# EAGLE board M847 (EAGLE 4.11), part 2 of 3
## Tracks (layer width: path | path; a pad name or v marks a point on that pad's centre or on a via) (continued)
C30 (continued)
  Top 0.254: E3.12 247.65,105.41 D354.C 247.01,116.21 245.75,116.21 D360.C 245.11,118.11 246.38,119.38 246.38,131.45 | 246.38,131.45 247.01,131.45 D353.C | 246.38,131.45 245.75,131.45 D359.C 245.11,133.35 246.38,134.62 246.38,146.69 | 246.38,146.69 247.01,146.69 D352.C | 246.38,146.69 245.75,146.69 D358.C 245.11,148.59 246.38,149.86 246.38,161.93 | D349.C 247.01,192.41 245.75,192.41 D355.C 245.11,191.77 246.38,190.5 246.38,177.17 | 246.38,161.93 247.01,161.93 D351.C | 246.38,161.93 245.75,161.93 D357.C 245.11,163.83 246.38,165.1 246.38,177.17 | 246.38,177.17 247.01,177.17 D350.C | 246.38,177.17 245.75,177.17 D356.C
C31
  Top 0.254: E3.10 254,99.06 D366.C 253.37,116.21 252.09,116.21 D372.C 251.46,118.11 252.73,119.38 252.73,131.45 | 252.73,131.45 253.37,131.45 D365.C | 252.73,131.45 252.09,131.45 D371.C 251.46,133.35 252.73,134.62 252.73,146.69 | 252.73,146.69 253.37,146.69 D364.C | 252.73,146.69 252.09,146.69 D370.C 251.46,148.59 252.73,149.86 252.73,161.93 | 252.73,161.93 253.37,161.93 D363.C | 252.73,161.93 252.09,161.93 D369.C 251.46,163.83 252.73,165.1 252.73,177.17 | 252.73,177.17 253.37,177.17 D362.C | 252.73,177.17 252.09,177.17 D368.C 251.46,179.07 250.19,180.34 250.19,190.5 251.46,191.77 D367.C
  Bottom 0.254: D367.C 252.09,192.41 253.37,192.41 D361.C
C32  (via drill 0.61)
  Top 0.254: v257.81,96.52 D384.C 258.44,116.21 259.71,116.21 D378.C 260.35,118.11 259.08,119.38 259.08,131.45 | 259.08,131.45 259.71,131.45 D377.C | 259.08,131.45 258.44,131.45 D383.C 257.81,133.35 259.08,134.62 259.08,146.69 | 259.08,146.69 259.71,146.69 D376.C | 259.08,146.69 258.44,146.69 D382.C 257.81,148.59 259.08,149.86 259.08,161.93 | D373.C 259.71,192.41 258.44,192.41 D379.C 257.81,191.77 259.08,190.5 259.08,177.17 | 259.08,161.93 259.71,161.93 D375.C | 259.08,161.93 258.44,161.93 D381.C 257.81,163.83 259.08,165.1 259.08,177.17 | 259.08,177.17 259.71,177.17 D374.C | 259.08,177.17 258.44,177.17 D380.C
  Bottom 0.254: v257.81,96.52 252.73,91.44 E3.8
CLR_GO\  (via drill 0.61)
  Top 0.254: v186.06,74.93 185.42,75.57 185.42,101.6 184.15,102.87 180.97,102.87 180.97,100.97 E10.4
  Bottom 0.254: v186.06,74.93 163.83,74.93 161.29,77.47 144.78,77.47 143.51,76.2 E18.13
D2\  (via drill 0.61)
  Top 0.254: E18.1 133.35,80.01 133.35,104.14 130.81,106.68 E19.4 | v13.34,107.95 13.34,93.35 E37.10
  Bottom 0.254: v13.34,107.95 14.61,109.22 105.41,109.22 106.05,109.86 | 106.05,109.86 107.95,111.76 E23.1 | 106.05,109.86 107.95,107.95 127,107.95 128.27,106.68 E19.4
D4  (via drill 0.61)
  Top 0.254: 17.14,86.36 17.14,97.16 E37.13 | 17.14,86.36 17.14,70.49 E36.10 | v102.23,99.06 v102.23,87.63 102.23,78.11 E22.2 | 17.14,86.36 25.4,86.36 v25.4,87
  Bottom 0.254: v102.23,99.06 103.5,100.33 146.05,100.33 148.59,97.79 161.29,97.79 163.83,100.33 166.37,100.33 170.18,104.14 E13.13 | v25.4,87 26.04,87.63 v102.23,87.63
DATA00\
  Top 0.254: E7.12 219.07,33.66 219.07,13.97 U$2.AR1
  Bottom 0.254: E4.10 234.95,35.56 233.68,34.29 223.52,34.29 222.25,35.56 E7.12
DATA01\  (via drill 0.61)
  Top 0.254: v223.52,41.91 223.52,40.64 E7.13 | v217.81,34.93 217.81,13.97 U$2.AS1
  Bottom 0.254: v223.52,41.91 233.68,41.91 234.95,43.18 E4.13 | E7.13 v217.81,34.93
DATA02\
  Top 0.254: E7.4 211.46,36.2 211.46,13.97 U$2.AU1
  Bottom 0.254: E7.4 214.63,38.1 215.9,39.37 226.06,39.37 227.33,38.1 E4.4
DATA03\  (via drill 0.61)
  Top 0.254: 210.82,38.1 208.28,35.56 208.28,13.97 U$2.AV1 | E7.3 210.82,38.1 | v210.19,48.26 210.82,47.63 210.82,38.1
  Bottom 0.254: v210.19,48.26 224.79,48.26 227.33,45.72 E4.1
DATA04\
  Top 0.254: E11.4 160.66,36.2 160.66,35.56 E14.10 151.13,31.75 151.13,13.97 U$2.BR1
DATA05\  (via drill 0.61)
  Top 0.254: E14.13 160.66,43.18 160.66,42.55 E11.3 | v145.41,41.91 145.41,14.61 146.05,13.97 U$2.BS1
  Bottom 0.254: v145.41,41.91 152.4,41.91 153.67,43.18 E14.13
DATA06\  (via drill 0.61)
  Top 0.254: v141.6,36.83 141.6,13.97 U$2.BU1
  Bottom 0.254: 144.78,36.83 v141.6,36.83 130.81,36.83 130.18,36.2 116.2,36.2 115.57,35.56 E21.10 | 144.78,36.83 146.05,38.1 E14.4 | 144.78,36.83 167.64,36.83 168.91,35.56 E11.12
DATA07\  (via drill 0.61)
  Top 0.254: v165.74,43.18 165.74,42.55 E11.13 | v137.16,48.9 137.16,13.97 U$2.BV1
  Bottom 0.254: 137.16,46.99 144.78,46.99 146.05,45.72 E14.1 148.59,45.72 149.86,44.45 164.47,44.45 v165.74,43.18 | 137.16,46.99 109.22,46.99 107.95,45.72 E21.1 | v137.16,48.9 137.16,46.99
DATA08\  (via drill 0.61)
  Top 0.254: E32.10 36.83,29.21 40.01,29.21 40.01,31.12 39.37,31.75 36.83,31.75 35.56,33.02 35.56,43.18 E29.1 | v55.88,34.29 59.69,38.1 E26.4 | v17.78,31.75 17.78,13.97 U$2.DR1
  Bottom 0.254: 33.02,34.29 v55.88,34.29 | 33.02,34.29 31.75,35.56 E32.10 | v17.78,31.75 20.32,34.29 33.02,34.29
DATA09\  (via drill 0.61)
  Top 0.254: v33.02,40.64 E32.13 28.57,41.28 28.57,31.12 v24.13,26.67 | v16.51,19.05 16.51,15.88 14.61,13.97 U$2.DS1
  Bottom 0.254: E26.3 52.07,40.64 50.8,39.37 40.64,39.37 39.37,38.1 E29.4 35.56,38.1 v33.02,40.64 | v16.51,19.05 v24.13,26.67
DATA10\  (via drill 0.61)
  Top 0.254: v10.16,33.02 10.16,30.48 8.26,28.58 8.26,13.97 U$2.DU1
  Bottom 0.254: 25.4,36.83 24.13,38.1 E32.4 | 25.4,36.83 43.18,36.83 44.45,35.56 E29.10 53.34,35.56 54.61,36.83 62.23,36.83 63.5,35.56 E26.12 | v10.16,33.02 13.97,36.83 25.4,36.83
DATA11\  (via drill 0.61)
  Top 0.254: v64.77,46.36 64.77,41.91 E26.13 | v5.08,28.58 5.08,13.97 U$2.DV1
  Bottom 0.254: v64.77,46.36 64.14,46.99 51.44,46.99 47.62,43.18 E29.13 44.45,43.18 43.18,44.45 25.4,44.45 24.13,45.72 E32.1 21.59,45.72 20.32,46.99 5.08,46.99 v5.08,28.58
DATA_EN  (via drill 0.61)
  Top 0.254: 43.81,69.85 36.83,69.85 36.2,70.49 36.2,73.66 E33.12 | 43.81,69.85 43.81,67.95 E30.9 | 43.81,69.85 v43.81,72.39
  Bottom 0.254: v43.81,72.39 69.85,72.39 71.12,73.66 E22.3
DATA_ENAB
  Top 0.254: E4.6 226.69,34.93 226.69,38.74 E4.3 | E4.9 237.49,33.02 243.84,26.67 248.92,26.67 248.92,22.23 257.18,13.97 U$2.AB1 | E32.6 24.77,34.93 24.77,38.74 E32.3 | 164.47,40.01 164.47,48.26 175.9,59.69 175.9,98.43 E13.12 | 164.47,40.01 163.83,39.37 155.57,39.37 155.57,40.01 E14.12 | 164.47,40.01 164.47,34.29 161.29,34.29 160.66,33.66 160.66,33.02 E14.9
  Bottom 0.254: E4.6 E4.9 | E4.12 E4.3 223.52,40.64 222.25,41.91 157.48,41.91 156.21,40.64 E14.12 E14.3 | E32.6 E32.9 31.75,33.02 33.02,31.75 144.78,31.75 146.05,33.02 E14.6 E14.9 | E32.3 E32.12
FIELD2DATA  (via drill 0.61)
  Top 0.254: E21.2 108.58,45.09 108.58,47.63 107.95,48.26 109.22,49.53 111.76,49.53 111.76,35.56 E21.9 | E29.6 E29.9 47.62,34.93 47.62,38.74 E29.12 | v24.77,54.61 24.77,69.22 E33.4 | v38.1,48.26 40.01,46.36 40.01,42.55 E29.3
  Bottom 0.254: v24.77,54.61 26.04,53.34 33.02,53.34 v38.1,48.26 | E29.12 E29.3 | E21.9 113.03,33.02 111.76,34.29 57.15,34.29 55.88,33.02 E29.9
FIELD\  (via drill 0.61)
  Top 0.254: E5.2 224.16,74.3 224.16,73.03 E5.4 223.52,68.58 223.52,59.69 v219.71,55.88
  Bottom 0.254: v219.71,55.88 5.08,55.88 5.08,76.2 6.35,77.47 16.51,77.47 17.14,78.11 20.95,78.11 21.59,78.74 E33.1
GND  (via drill 0.61)
  Top 0.635: E21.7 107.31,29.85 107.31,25.4 v117.47,15.24 120.65,15.24 120.65,13.97 U$2.CC1 | 79.38,24.77 79.38,13.97 U$2.CT1 | 79.38,24.77 79.38,26.67 | 79.38,26.67 v79.38,30.48 79.38,31.75 78.74,32.39 F1.1 | 79.38,26.67 v90.81,15.24 92.08,13.97 U$2.CN1 | E32.7 22.23,29.85 22.23,13.97 U$2.DN1 | 50.8,15.24 v44.45,15.24 43.18,13.97 U$2.DF1 | 50.8,15.24 50.8,13.97 U$2.DC1 | v9.53,15.24 9.53,13.97 U$2.DT1 11.43,13.97 15.24,17.78 v15.24,19.69 | 50.8,15.24 52.7,17.15 52.7,22.23 C9.+ | E24.7 88.27,93.35 88.27,111.76 C40.2 | E27.1 62.23,80.01 C47.2 62.23,85.09 E28.7 | E25.7 73.03,93.35 73.03,111.76 C43.2 | E30.7 39.37,62.23 C44.2 38.73,50.8 34.29,46.36 34.29,33.02 36.83,30.48 E29.7 | E33.7 23.5,62.87 23.5,50.8 C46.2 | E35.1 8.89,46.99 C42.2 8.89,62.23 E36.7 9.53,65.41 9.53,83.82 C38.2 8.89,84.46 8.26,85.09 8.26,88.27 E37.8 | 40.01,88.9 40.01,90.81 E31.7 | 40.01,88.9 40.01,85.09 39.37,84.46 C33.2 | 40.01,88.9 29.21,88.9 29.21,91.44 E34.7 29.84,93.35 29.84,111.76 C41.2 | v78.74,24.77 79.38,24.77 | E14.7 149.22,32.39 149.22,50.8 C28.2 148.59,62.23 E15.7 | v144.15,30.48 144.15,13.97 U$2.BT1 | F0.1 S11.1 S10.1 S8.1 S9.1 | 106.05,77.47 106.05,83.82 C39.2 | 106.05,77.47 106.05,65.41 E22.7 104.78,62.87 104.78,54.61 107.95,51.44 C36.2 | 106.05,77.47 107.95,77.47 108.58,78.11 108.58,95.89 E23.7 | C23.2 163.83,51.44 164.47,52.07 164.47,62.87 E12.7 168.91,67.31 v168.91,73.66 167,75.57 167,83.82 C24.2 166.37,90.17 E13.7 | C27.2 151.13,84.46 150.5,85.09 150.5,95.89 E16.7 | E20.1 120.65,80.01 C35.2 | C30.2 136.53,83.82 136.53,74.3 v137.16,73.66 136.53,73.03 136.53,65.41 E18.7 133.35,62.23 C29.2 133.35,46.99 E17.1
  Top 0.635: v127.64,43.82 C8.- | E7.8 212.72,27.31 212.72,13.97 U$2.AT2 | 227.33,15.24 227.33,13.97 U$2.AN2 | 227.33,15.24 227.33,29.21 E4.7 | 245.11,15.24 245.11,13.97 U$2.AF1 | C18.2 245.11,15.24 | 245.11,15.24 227.33,15.24 | U$2.BC1 184.15,13.97 184.15,15.24 v177.8,15.24 176.53,13.97 U$2.BF1 174.62,13.97 167,21.59 | v155.57,15.24 155.57,13.97 U$2.BN2 157.48,13.97 157.48,22.86 E11.8 163.19,27.31 163.19,25.4 167,21.59 | E1.1 245.11,46.99 C17.2 245.11,51.44 245.75,52.07 245.75,82.55 C16.2 | E5.7 229.87,59.69 C14.2 | S5.1 S4.1 S6.1 S7.1 187.96,45.72 C10.- 179.71,37.47 179.71,34.29 167,21.59 | S1.1 S0.1 S2.1 S3.1 | v149.22,121.92 151.13,120.02 C26.2 | C31.2 130.81,120.02 134.62,123.83 C7.2 | C32.2 110.49,117.48 111.76,118.75 R52.1 112.39,139.7 113.67,140.97 C6.2 | C12.2 227.33,84.46 227.97,85.09 227.97,90.81 E6.7 | E2.1 245.11,80.01 C16.2 | C16.2 245.11,90.17 E3.7 245.75,93.35 245.75,111.76 C15.2
  Bottom 0.635: U$2.CF2 113.03,13.97 114.3,15.24 v117.47,15.24 119.38,15.24 120.65,13.97 U$2.CC2 | U$2.CT1 81.28,13.97 82.55,15.24 v90.81,15.24 92.08,13.97 U$2.CN1 | F1.1 F2.1 | v79.38,30.48 E21.7 | v44.45,15.24 43.18,13.97 U$2.DF2 | v44.45,15.24 49.53,15.24 50.8,13.97 U$2.DC2 | v44.45,15.24 25.4,15.24 24.13,13.97 U$2.DN1 | v9.53,15.24 9.53,13.97 U$2.DT1 | 41.91,27.94 46.35,23.5 52.7,23.5 C9.+ 53.98,23.5 55.24,23.5 56.52,24.77 | 41.91,27.94 39.37,30.48 E29.7 | 56.52,24.77 59.69,27.94 E26.8 | v15.24,19.69 23.5,27.94 35.56,27.94 | 41.91,27.94 35.56,27.94 | 35.56,27.94 31.75,31.75 25.4,31.75 24.13,30.48 E32.7 | E28.7 57.15,91.44 58.42,92.71 68.58,92.71 69.85,91.44 E25.7 | C46.2 23.5,50.8 22.23,49.53 10.79,49.53 9.53,50.8 C42.2 | E30.7 36.83,63.5 35.56,62.23 27.94,62.23 26.67,63.5 E33.7 | E37.8 E37.9 16.51,88.9 17.78,90.17 24.13,90.17 | 24.13,90.17 24.13,91.44 E34.7 | 24.13,90.17 C45.2 | 27.3,113.03 10.79,113.03 9.53,111.76 C34.2 | 27.3,113.03 28.57,111.76 C41.2 | 40.01,113.03 41.27,111.76 C37.2 | 40.01,113.03 27.3,113.03 | 55.24,113.03 56.52,111.76 C48.2 | 55.24,113.03 40.01,113.03 | 55.24,113.03 70.48,113.03 71.75,111.76 C43.2 73.03,111.76 74.3,113.03 85.72,113.03 87,111.76 C40.2 87.63,118.75 113.03,118.75 | 56.52,24.77 v78.74,24.77 | E14.7 v144.15,30.48 | S9.1 104.78,48.26 107.31,50.8 C36.2 | v168.91,73.66 E12.12 | E19.8 E19.9 E16.7 | 133.99,82.55 135.25,83.82 C30.2 | 133.99,82.55 122.56,82.55 | 122.56,82.55 121.28,83.82 C35.2 | v137.16,73.66 E18.12 | v127.64,43.82 129.54,45.72 E17.1 | 149.22,82.55 150.5,83.82 C27.2 | 149.22,82.55 133.99,82.55 | 149.22,82.55 164.47,82.55 165.74,83.82 C24.2 | 122.56,82.55 107.31,82.55 106.05,83.82 C39.2
  Bottom 0.635: E15.7 148.59,63.5 147.32,62.23 137.16,62.23 135.89,63.5 E18.7 | 212.72,15.24 212.72,27.31 E7.8 | 212.72,15.24 212.72,13.97 U$2.AT2 | 212.72,15.24 224.16,15.24 225.43,13.97 U$2.AN2 227.33,13.97 233.04,19.69 245.11,19.69 | 245.11,19.69 245.11,15.24 | 245.11,15.24 245.11,13.97 U$2.AF2 | 245.11,19.69 C18.2 245.75,25.4 249.56,29.21 252.73,29.21 258.44,34.93 258.44,37.47 C11.- 258.44,38.74 258.44,46.99 246.38,46.99 245.11,45.72 E1.1 242.57,45.72 238.76,49.53 227.97,49.53 | 245.11,15.24 252.73,15.24 254,13.97 U$2.AC2 | U$2.BF2 176.53,13.97 v177.8,15.24 182.88,15.24 184.15,13.97 U$2.BC2 | v155.57,15.24 155.57,13.97 U$2.BN2 | 212.72,49.53 214,50.8 C13.2 | 212.72,49.53 207.65,49.53 206.38,48.26 S3.1 | S1.1 S5.1 | 227.97,49.53 229.24,50.8 C14.2 | 227.97,49.53 212.72,49.53 | v149.22,121.92 147.32,123.83 T2.1 | 128.91,120.65 130.18,119.38 C31.2 | 128.91,120.65 114.94,120.65 113.03,118.75 | 113.03,118.75 111.12,116.84 C32.2 | 146.69,118.11 139.06,118.11 136.53,120.65 128.91,120.65 | 146.69,118.11 149.22,118.11 150.5,116.84 C26.2 | 185.42,90.17 184.15,91.44 E10.7 | 185.42,90.17 195.58,90.17 196.85,91.44 E9.7 199.39,91.44 200.66,90.17 215.9,90.17 | 215.9,90.17 222.25,83.82 C12.2 | 215.9,90.17 214.63,91.44 E8.7 | 168.28,113.03 167,111.76 C25.2 | 168.28,113.03 182.25,113.03 183.51,111.76 C22.2 184.78,111.76 186.06,110.49 197.49,110.49 | 197.49,110.49 198.75,111.76 C21.2 | 212.72,110.49 214,111.76 C20.2 | 197.49,110.49 212.72,110.49 | 227.97,110.49 229.24,111.76 C19.2 | 212.72,110.49 227.97,110.49 | 227.97,110.49 243.21,110.49 244.47,111.76 C15.2 | E6.7 229.87,91.44 231.14,90.17 241.3,90.17 242.57,91.44 E3.7
  Bottom 0.635: 146.69,118.11 146.69,110.49 153.67,110.49 156.21,113.03 168.28,113.03 | 185.42,90.17 167.64,90.17 166.37,91.44 E13.7
INIT_ADD\
  Top 0.254: E26.9 58.42,17.78 58.42,13.97 U$2.DA1 | E5.6 224.16,64.14 224.16,42.55 224.79,41.91 224.79,31.75 E7.9
  Bottom 0.254: E7.9 218.44,27.94 217.17,29.21 212.09,29.21 211.46,28.58 172.09,28.58 171.45,27.94 E11.9 168.91,27.94 167.64,26.67 161.29,26.67 160.66,27.31 70.48,27.31 69.85,27.94 E26.9
INITIALIZE  (via drill 0.61)
  Top 0.254: E27.11 67.94,71.76 67.94,73.03 E27.12 | v73.66,71.12 73.66,33.66 73.03,33.02 73.03,22.23 v76.2,19.05 | v83.19,16.51 85.72,13.97 U$2.CR1
  Bottom 0.254: v76.2,19.05 78.74,16.51 v83.19,16.51 | v73.66,71.12 E27.11
KEY_CONTROL\  (via drill 0.61)
  Top 0.254: v108.58,26.04 108.58,36.2 E21.4
  Bottom 0.254: v108.58,26.04 102.87,20.32 39.37,20.32 36.2,17.15 10.16,17.15 6.99,13.97 U$2.DU2
LA_ENABLE\  (via drill 0.61)
  Top 0.254: v100.97,19.05 100.97,67.95 E22.4
  Bottom 0.254: v100.97,19.05 101.6,19.69 131.44,19.69 132.08,20.32 152.4,20.32 158.75,13.97 U$2.BM2
LAST_WORD
  Bottom 0.254: E12.2 166.37,76.2 167.64,77.47 247.01,77.47 251.46,81.92 251.46,90.17 250.19,90.17 249.56,90.81 249.56,93.98 E3.9 252.09,94.62 254,94.62 254,104.14 252.73,105.41 238.76,105.41 237.49,104.14 E6.13
LOAD_PULSE
  Top 0.254: E33.8 28.57,65.41 28.57,74.3 E33.13 | R29.1 R28.1 | E36.2 6.99,76.84 6.99,78.11 E36.1
  Bottom 0.254: E36.2 E36.13 16.51,76.2 17.78,77.47 27.94,77.47 29.21,76.2 E33.13 | R29.1 108.58,177.8 106.05,175.26 6.35,175.26 3.81,172.72 3.81,79.38 6.99,79.38 E36.1
LW\@TP4
  Top 0.254: E15.4 149.22,71.76 149.22,73.03 E15.3
MEM_START\  (via drill 0.61)
  Top 0.254: v107.31,59.06 v107.31,76.2 | v232.41,57.15 233.68,55.88 v233.68,18.42
  Bottom 0.254: v107.31,76.2 106.68,76.2 E22.1 | v107.31,59.06 109.22,57.15 v232.41,57.15 | v233.68,18.42 238.12,13.97 U$2.AJ2
MSIR_DISABLE\  (via drill 0.61)
  Top 0.254: v93.34,76.84 86.36,69.85 86.36,57.79 77.47,48.9 77.47,47.63 78.74,46.36 78.74,34.93 77.47,33.66 77.47,16.51 74.93,13.97 U$2.CV1
  Bottom 0.254: v93.34,76.84 95.89,76.84 97.79,74.93 109.22,74.93 110.49,76.2 E22.13
N$1
  Top 0.254: E31.1 40.01,106.05 40.01,104.78 E31.2 43.18,101.6 43.18,97.79 49.53,97.79 53.98,93.35 53.98,80.65 E27.3
N$2  (via drill 0.61)
  Top 0.254: S3.2 205.74,33.66 207.01,34.93 R7.1 207.01,43.18 v209.55,45.72
  Bottom 0.254: v209.55,45.72 E7.1
N$3  (via drill 0.61)
  Top 0.254: v43.18,47.63 43.18,40.64 E29.5 | R1.1 77.47,46.36 76.2,47.63 F2.2 | v109.22,48.26 109.22,35.56 E21.8
  Bottom 0.254: v43.18,47.63 43.81,48.26 F2.2 | v109.22,48.26 107.95,46.99 79.38,46.99 78.11,45.72 R1.1
N$4  (via drill 0.61)
  Top 0.254: v49.53,46.36 49.53,34.29 E29.8 | R2.1 80.01,46.36 78.74,47.63 F1.2
  Bottom 0.254: v49.53,46.36 50.8,47.63 74.93,47.63 75.56,46.99 76.83,46.99 78.11,48.26 F1.2 | E21.3 105.41,40.64 102.87,43.18 83.19,43.18 80.64,45.72 R2.1
N$5  (via drill 0.61)
  Top 0.254: R3.1 82.55,34.93 81.28,33.66 F0.2 81.28,26.04 82.55,24.77 93.98,24.77 v93.98,36.83 | E29.2 36.2,41.28 36.2,34.93 36.83,34.29 43.81,34.29 43.81,36.2 E29.11
  Bottom 0.254: v93.98,36.83 93.34,37.47 71.75,37.47 69.85,39.37 54.61,39.37 53.98,40.01 52.7,40.01 50.8,38.1 E29.11
N$6
  Top 0.254: R6.1 204.47,34.93 203.2,33.66 S2.2
  Bottom 0.254: E7.6 212.09,33.02 210.82,31.75 205.1,31.75 203.84,33.02 S2.2
N$7
  Top 0.254: R5.1 201.93,34.93 200.66,33.66 S0.2
  Bottom 0.254: E7.10 219.71,30.48 215.9,34.29 203.84,34.29 202.56,35.56 R5.1
N$8  (via drill 0.61)
  Top 0.254: S1.2 198.12,33.66 199.39,34.93 R4.1 199.39,38.1 v205.74,44.45
  Bottom 0.254: v205.74,44.45 218.44,44.45 219.71,43.18 E7.15
N$9
  Top 0.254: E7.14 216.53,45.09 216.53,60.96 213.36,64.14 213.36,69.22 212.72,69.85 209.55,69.85 R8.2 209.55,67.95 208.28,66.68 I1.2
N$10
  Top 0.254: E7.11 222.88,34.93 222.88,36.2 222.25,36.83 215.9,36.83 215.9,59.69 210.82,64.77 I0.2 210.82,66.68 212.09,67.95 R9.2
N$11
  Top 0.254: R10.2 207.01,67.95 205.74,66.68 I2.2 205.74,65.41 212.09,59.06 212.09,51.44 215.26,48.26 215.26,37.47 E7.5
N$12
  Top 0.254: E7.2 211.46,45.09 211.46,57.15 203.2,65.41 I3.2 203.2,66.68 204.47,67.95 R11.2
N$13  (via drill 0.61)
  Top 0.254: 20.32,67.31 13.97,67.31 13.34,67.95 13.34,71.76 E36.12 | 20.32,67.31 20.32,73.66 E33.2 | 25.4,47.63 26.67,48.9 26.67,50.17 34.29,57.79 34.29,64.77 E30.5 | 25.4,47.63 20.32,47.63 20.32,67.31 | v27.94,41.91 25.4,44.45 25.4,47.63
  Bottom 0.254: v27.94,41.91 69.85,41.91 73.66,38.1 102.87,38.1 105.41,35.56 E21.5
N$14  (via drill 0.61)
  Top 0.254: v198.12,44.45 196.85,43.18 R15.1 196.85,34.93 195.58,33.66 S5.2
  Bottom 0.254: v198.12,44.45 168.91,44.45 168.28,45.09 164.47,45.09 163.83,45.72 E11.1
N$15
  Top 0.254: R14.1 194.31,34.93 193.04,33.66 S4.2
  Bottom 0.254: E11.6 163.83,33.02 165.1,31.75 171.45,31.75 173.35,33.66 186.69,33.66 187.32,34.29 191.13,34.29 192.41,33.02 S4.2
N$16
  Top 0.254: R13.1 191.77,34.93 190.5,33.66 S6.2
  Bottom 0.254: E11.10 171.45,30.48 172.72,31.75 188.59,31.75 189.87,33.02 S6.2
N$17  (via drill 0.61)
  Top 0.254: v187.32,43.18 189.23,41.28 R12.1 189.23,34.93 187.96,33.66 S7.2
  Bottom 0.254: E11.15 v187.32,43.18
N$18
  Top 0.254: E11.14 193.04,63.5 I7.2 193.04,66.68 194.31,67.95 R16.2
N$19
  Top 0.254: E11.11 195.58,58.42 I6.2 195.58,66.68 196.85,67.95 R17.2
N$20  (via drill 0.61)
  Top 0.254: v191.13,40.64 195.58,45.09 195.58,46.36 196.85,47.63 196.85,64.14 198.12,65.41 I4.2 198.12,66.68 199.39,67.95 R18.2
  Bottom 0.254: v191.13,40.64 184.78,34.29 165.1,34.29 163.83,35.56 E11.5
N$21  (via drill 0.61)
  Top 0.254: v160.66,60.33 160.66,45.09 E11.2 | R19.2 201.93,67.95 200.66,66.68 I5.2
  Bottom 0.254: v160.66,60.33 162.56,62.23 168.91,62.23 171.45,64.77 198.75,64.77 200.03,66.04 I5.2
N$22
  Bottom 0.254: E33.6 24.13,66.04 25.4,67.31 35.56,67.31 36.83,66.04 E30.6
N$23  (via drill 0.61)
  Top 0.254: v87,40.64 92.08,35.56 R23.1 92.71,34.93 91.44,33.66 S9.2
  Bottom 0.254: v87,40.64 80.64,40.64 74.3,46.99 67.31,46.99 65.41,45.09 62.87,45.09 62.23,45.72 E26.1
N$24  (via drill 0.61)
  Top 0.254: v66.04,36.83 62.23,33.02 E26.6 | S8.2 88.9,33.66 90.17,34.93 R22.1
  Bottom 0.254: v66.04,36.83 88.27,36.83 89.53,35.56 R22.1
N$25  (via drill 0.61)
  Top 0.254: v71.75,26.04 71.75,27.31 E26.10 | v82.55,26.04 86.36,29.85 S10.2 86.36,33.66 87.63,34.93 R21.1
  Bottom 0.254: v71.75,26.04 v82.55,26.04
N$26  (via drill 0.61)
  Top 0.254: v81.92,39.37 85.09,36.2 R20.1 85.09,34.93 83.82,33.66 S11.2
  Bottom 0.254: v81.92,39.37 73.66,39.37 69.85,43.18 E26.15
N$27  (via drill 0.61)
  Top 0.254: v71.12,65.41 71.12,43.18 E26.14 | R24.2 77.47,67.95 76.2,66.68 I11.2
  Bottom 0.254: v71.12,65.41 71.75,66.04 I11.2
N$28  (via drill 0.61)
  Top 0.254: v74.3,33.02 74.3,60.96 78.74,65.41 I10.2 78.74,66.68 80.01,67.95 R25.2
  Bottom 0.254: E26.11 v74.3,33.02
N$29  (via drill 0.61)
  Top 0.254: v63.5,66.04 63.5,38.1 E26.5 | R26.2 82.55,67.95 81.28,66.68 I8.2
  Bottom 0.254: v63.5,66.04 64.77,67.31 79.38,67.31 80.64,66.04 I8.2
N$30  (via drill 0.61)
  Top 0.254: v75.56,44.45 74.93,45.09 74.93,56.52 83.82,65.41 I9.2 83.82,66.68 85.09,67.95 R27.2
  Bottom 0.254: v75.56,44.45 63.5,44.45 62.23,43.18 E26.2
N$31
  Top 0.254: R30.1 114.3,188.6 111.76,191.14 T1.3
N$32
  Top 0.254: E34.5 26.04,94.62 26.04,90.81 34.29,82.55 42.55,82.55 42.55,99.7 E31.3
N$33
  Top 0.254: E1.11 250.82,38.74 250.82,40.01 E1.12 255.27,44.45 255.27,184.15 252.73,186.69 252.73,200.66 254,201.93 D361.A | D193.A 164.47,202.57 164.47,201.3 161.93,201.3 161.29,201.93 161.29,203.2 R40.2 149.22,203.2 149.22,201.93 146.69,201.93 146.05,202.57 104.78,202.57 D181.A
  Bottom 0.254: 13.34,205.11 10.79,205.11 D1.A | 13.34,205.11 D13.A | 19.68,205.11 13.34,205.11 | 19.68,205.11 D25.A | 26.04,205.11 19.68,205.11 | 26.04,205.11 D37.A | 32.38,205.11 26.04,205.11 | 32.38,205.11 D49.A | 38.73,205.11 32.38,205.11 | 38.73,205.11 D61.A | 45.09,205.11 38.73,205.11 | 45.09,205.11 D73.A | 51.44,205.11 45.09,205.11 | 51.44,205.11 D85.A | 51.44,205.11 57.78,205.11 | 57.78,205.11 D97.A | 57.78,205.11 64.14,205.11 | 64.14,205.11 D109.A | 64.14,205.11 70.48,205.11 | 70.48,205.11 D121.A | 70.48,205.11 76.83,205.11 | 76.83,205.11 D133.A | 76.83,205.11 83.19,205.11 | 83.19,205.11 D145.A | 83.19,205.11 89.53,205.11 | 89.53,205.11 D157.A | 89.53,205.11 95.89,205.11 | 95.89,205.11 D169.A | 95.89,205.11 102.23,205.11 D181.A | 169.54,205.11 167,205.11 D193.A | 169.54,205.11 D205.A | 169.54,205.11 175.9,205.11 | 175.9,205.11 D217.A | 175.9,205.11 182.25,205.11 | 182.25,205.11 D229.A | 182.25,205.11 188.59,205.11 | 188.59,205.11 D241.A | 188.59,205.11 194.94,205.11 | 194.94,205.11 D253.A | 194.94,205.11 201.29,205.11 | 201.29,205.11 D265.A | 201.29,205.11 207.65,205.11 | 207.65,205.11 D277.A | 207.65,205.11 214,205.11 | 214,205.11 D289.A | 214,205.11 220.34,205.11 | 220.34,205.11 D301.A | 220.34,205.11 226.69,205.11 | 226.69,205.11 D313.A | 226.69,205.11 233.04,205.11 | 233.04,205.11 D325.A | 233.04,205.11 239.4,205.11 | 239.4,205.11 D337.A | 239.4,205.11 245.75,205.11 | 245.75,205.11 D349.A | 245.75,205.11 252.09,205.11 | 252.09,205.11 D361.A | 252.09,205.11 258.44,205.11 D373.A
N$34  (via drill 0.61)
  Top 0.254: v157.48,127.64 153.03,132.08 R51.2 | E35.10 14.61,34.93 14.61,33.66 E35.9 17.14,31.12 17.14,29.85 16.51,29.21 12.06,29.21 12.06,104.78 7.62,109.22 7.62,124.46 6.35,125.73 D12.A
  Bottom 0.254: 167,125.1 164.47,125.1 D204.A 161.93,127.64 v157.48,127.64 107.31,127.64 104.78,125.1 99.69,125.1 | 167,125.1 D216.A | 167,125.1 173.35,125.1 | 173.35,125.1 D228.A | 173.35,125.1 179.71,125.1 | 179.71,125.1 D240.A | 179.71,125.1 186.06,125.1 | 186.06,125.1 D252.A | 186.06,125.1 192.41,125.1 | 192.41,125.1 D264.A | 192.41,125.1 198.75,125.1 | 198.75,125.1 D276.A | 198.75,125.1 205.1,125.1 | 205.1,125.1 D288.A | 205.1,125.1 211.46,125.1 | 211.46,125.1 D300.A | 211.46,125.1 217.81,125.1 | 217.81,125.1 D312.A | 217.81,125.1 224.16,125.1 | 224.16,125.1 D324.A | 224.16,125.1 230.5,125.1 | 230.5,125.1 D336.A | 230.5,125.1 236.85,125.1 | 236.85,125.1 D348.A | 236.85,125.1 243.21,125.1 | 243.21,125.1 D360.A | 243.21,125.1 249.56,125.1 | 249.56,125.1 D372.A | 249.56,125.1 255.91,125.1 D384.A | 10.79,125.1 8.26,125.1 D12.A | 10.79,125.1 D24.A | 17.14,125.1 10.79,125.1 | 17.14,125.1 D36.A | 23.5,125.1 17.14,125.1 | 23.5,125.1 D48.A | 29.84,125.1 23.5,125.1 | 29.84,125.1 D60.A | 36.2,125.1 29.84,125.1 | 36.2,125.1 D72.A | 42.55,125.1 36.2,125.1 | 42.55,125.1 D84.A | 48.9,125.1 42.55,125.1 | 48.9,125.1 D96.A | 55.24,125.1 48.9,125.1 | 55.24,125.1 D108.A | 61.59,125.1 55.24,125.1 | 61.59,125.1 D120.A | 67.94,125.1 61.59,125.1 | 67.94,125.1 D132.A | 74.3,125.1 67.94,125.1 | 74.3,125.1 D144.A | 80.64,125.1 74.3,125.1 | 80.64,125.1 D156.A | 87,125.1 80.64,125.1 | 87,125.1 D168.A | 93.34,125.1 87,125.1 | 93.34,125.1 D180.A | 99.69,125.1 93.34,125.1 | 99.69,125.1 D192.A
N$35  (via drill 0.61)
  Top 0.254: E35.11 14.61,38.74 14.61,40.01 E35.12 | v10.16,40.64 10.79,41.28 v10.79,104.78
  Bottom 0.254: 167,140.34 164.47,140.34 D203.A 162.56,143.51 149.22,143.51 147.96,142.24 R50.2 106.68,142.24 104.78,140.34 99.69,140.34 | 167,140.34 D215.A | 167,140.34 173.35,140.34 | 173.35,140.34 D227.A | 173.35,140.34 179.71,140.34 | 179.71,140.34 D239.A | 179.71,140.34 186.06,140.34 | 186.06,140.34 D251.A | 186.06,140.34 192.41,140.34 | 192.41,140.34 D263.A | 192.41,140.34 198.75,140.34 | 198.75,140.34 D275.A | 198.75,140.34 205.1,140.34 | 205.1,140.34 D287.A | 205.1,140.34 211.46,140.34 | 211.46,140.34 D299.A | 211.46,140.34 217.81,140.34 | 217.81,140.34 D311.A | 217.81,140.34 224.16,140.34 | 224.16,140.34 D323.A | 224.16,140.34 230.5,140.34 | 230.5,140.34 D335.A | 230.5,140.34 236.85,140.34 | 236.85,140.34 D347.A | 236.85,140.34 243.21,140.34 | 243.21,140.34 D359.A | 243.21,140.34 249.56,140.34 | 249.56,140.34 D371.A | 249.56,140.34 255.91,140.34 D383.A | 10.79,140.34 8.26,140.34 D11.A 5.71,141.61 5.08,141.61 5.08,112.4 10.79,106.68 v10.79,104.78 | 10.79,140.34 D23.A | 17.14,140.34 10.79,140.34 | 17.14,140.34 D35.A | 23.5,140.34 17.14,140.34 | 23.5,140.34 D47.A | 29.84,140.34 23.5,140.34 | 29.84,140.34 D59.A | 36.2,140.34 29.84,140.34 | 36.2,140.34 D71.A | 42.55,140.34 36.2,140.34 | 42.55,140.34 D83.A | 48.9,140.34 42.55,140.34 | 48.9,140.34 D95.A | 55.24,140.34 48.9,140.34 | 55.24,140.34 D107.A | 61.59,140.34 55.24,140.34 | 61.59,140.34 D119.A | 67.94,140.34 61.59,140.34 | 67.94,140.34 D131.A | 74.3,140.34 67.94,140.34 | 74.3,140.34 D143.A | 80.64,140.34 74.3,140.34 | 80.64,140.34 D155.A | 87,140.34 80.64,140.34 | 87,140.34 D167.A | 93.34,140.34 87,140.34 | 93.34,140.34 D179.A | 99.69,140.34 93.34,140.34 | 99.69,140.34 D191.A | v10.16,40.64 E35.12
N$36
  Top 0.254: E35.7 6.99,31.12 6.99,32.39 E35.6 3.81,36.83 3.81,172.72 5.71,174.63 7.62,174.63 7.62,160.02 6.35,158.75 D10.A
  Bottom 0.254: 167,155.58 164.47,155.58 D202.A 162.56,158.75 149.22,158.75 147.96,157.48 R49.2 146.69,157.48 144.78,155.58 99.69,155.58 | 167,155.58 D214.A | 167,155.58 173.35,155.58 | 173.35,155.58 D226.A | 173.35,155.58 179.71,155.58 | 179.71,155.58 D238.A | 179.71,155.58 186.06,155.58 | 186.06,155.58 D250.A | 186.06,155.58 192.41,155.58 | 192.41,155.58 D262.A | 192.41,155.58 198.75,155.58 | 198.75,155.58 D274.A | 198.75,155.58 205.1,155.58 | 205.1,155.58 D286.A | 205.1,155.58 211.46,155.58 | 211.46,155.58 D298.A | 211.46,155.58 217.81,155.58 | 217.81,155.58 D310.A | 217.81,155.58 224.16,155.58 | 224.16,155.58 D322.A | 224.16,155.58 230.5,155.58 | 230.5,155.58 D334.A | 230.5,155.58 236.85,155.58 | 236.85,155.58 D346.A | 236.85,155.58 243.21,155.58 | 243.21,155.58 D358.A | 243.21,155.58 249.56,155.58 | 249.56,155.58 D370.A | 249.56,155.58 255.91,155.58 D382.A | 10.79,155.58 8.26,155.58 D10.A | 10.79,155.58 D22.A | 17.14,155.58 10.79,155.58 | 17.14,155.58 D34.A | 23.5,155.58 17.14,155.58 | 23.5,155.58 D46.A | 29.84,155.58 23.5,155.58 | 29.84,155.58 D58.A | 36.2,155.58 29.84,155.58 | 36.2,155.58 D70.A | 42.55,155.58 36.2,155.58 | 42.55,155.58 D82.A | 48.9,155.58 42.55,155.58 | 48.9,155.58 D94.A | 55.24,155.58 48.9,155.58 | 55.24,155.58 D106.A | 61.59,155.58 55.24,155.58 | 61.59,155.58 D118.A | 67.94,155.58 61.59,155.58 | 67.94,155.58 D130.A | 74.3,155.58 67.94,155.58 | 74.3,155.58 D142.A | 80.64,155.58 74.3,155.58 | 80.64,155.58 D154.A | 87,155.58 80.64,155.58 | 87,155.58 D166.A | 93.34,155.58 87,155.58 | 93.34,155.58 D178.A | 99.69,155.58 93.34,155.58 | 99.69,155.58 D190.A
N$37
  Top 0.254: E17.9 139.06,33.66 139.06,34.93 E17.10 137.79,37.47 137.79,48.26 144.78,55.25 144.78,71.12 147.32,73.66 147.32,78.74 151.13,82.55 153.67,82.55 153.67,100.33 156.21,102.87 160.66,102.87 160.66,184.79 162.56,186.69 D200.A
  Bottom 0.254: 10.79,186.06 8.26,186.06 D8.A | 10.79,186.06 D20.A | 17.14,186.06 10.79,186.06 | 17.14,186.06 D32.A | 23.5,186.06 17.14,186.06 | 23.5,186.06 D44.A | 29.84,186.06 23.5,186.06 | 29.84,186.06 D56.A | 36.2,186.06 29.84,186.06 | 36.2,186.06 D68.A | 42.55,186.06 36.2,186.06 | 42.55,186.06 D80.A | 48.9,186.06 42.55,186.06 | 48.9,186.06 D92.A | 55.24,186.06 48.9,186.06 | 55.24,186.06 D104.A | 61.59,186.06 55.24,186.06 | 61.59,186.06 D116.A | 67.94,186.06 61.59,186.06 | D128.A 67.94,186.06 | 67.94,186.06 74.3,186.06 | 74.3,186.06 D140.A | 74.3,186.06 80.64,186.06 | 80.64,186.06 D152.A | 80.64,186.06 87,186.06 | 87,186.06 D164.A | 87,186.06 93.34,186.06 | 93.34,186.06 D176.A | 93.34,186.06 99.69,186.06 D188.A 103.5,186.06 144.78,186.06 146.69,187.96 R47.2 147.96,187.96 149.22,189.23 162.56,189.23 D200.A 164.47,186.06 167,186.06 | 167,186.06 D212.A | 167,186.06 173.35,186.06 | 173.35,186.06 D224.A | 173.35,186.06 179.71,186.06 | 179.71,186.06 D236.A | 179.71,186.06 186.06,186.06 | 186.06,186.06 D248.A | 186.06,186.06 192.41,186.06 | 192.41,186.06 D260.A | 192.41,186.06 198.75,186.06 | 198.75,186.06 D272.A | 198.75,186.06 205.1,186.06 | 205.1,186.06 D284.A | 205.1,186.06 211.46,186.06 | 211.46,186.06 D296.A | 211.46,186.06 217.81,186.06 | 217.81,186.06 D308.A | 217.81,186.06 224.16,186.06 | 224.16,186.06 D320.A | 224.16,186.06 230.5,186.06 | 230.5,186.06 D332.A | 230.5,186.06 236.85,186.06 | 236.85,186.06 D344.A | 236.85,186.06 243.21,186.06 | 243.21,186.06 D356.A | 243.21,186.06 249.56,186.06 | 249.56,186.06 D368.A | 249.56,186.06 255.91,186.06 D380.A
N$38  (via drill 0.61)
  Top 0.254: E17.11 139.06,38.74 139.06,40.01 E17.12 | v98.42,39.37 94.61,43.18 94.61,88.27 91.44,91.44 91.44,104.78 90.81,105.41 90.81,113.67 93.98,116.84 93.98,200.66 95.25,201.93 D175.A
  Bottom 0.254: 167,201.3 164.47,201.3 D199.A 162.56,204.47 149.22,204.47 147.96,203.2 R46.2 146.69,203.2 144.78,201.3 99.69,201.3 | 167,201.3 D211.A | 167,201.3 173.35,201.3 | 173.35,201.3 D223.A | 173.35,201.3 179.71,201.3 | 179.71,201.3 D235.A | 179.71,201.3 186.06,201.3 | 186.06,201.3 D247.A | 186.06,201.3 192.41,201.3 | 192.41,201.3 D259.A | 192.41,201.3 198.75,201.3 | 198.75,201.3 D271.A | 198.75,201.3 205.1,201.3 | 205.1,201.3 D283.A | 205.1,201.3 211.46,201.3 | 211.46,201.3 D295.A | 211.46,201.3 217.81,201.3 | 217.81,201.3 D307.A | 217.81,201.3 224.16,201.3 | 224.16,201.3 D319.A | 224.16,201.3 230.5,201.3 | 230.5,201.3 D331.A | 230.5,201.3 236.85,201.3 | 236.85,201.3 D343.A | 236.85,201.3 243.21,201.3 | 243.21,201.3 D355.A | 243.21,201.3 249.56,201.3 | 249.56,201.3 D367.A | 249.56,201.3 255.91,201.3 D379.A | 10.79,201.3 8.26,201.3 D7.A | 10.79,201.3 D19.A | 17.14,201.3 10.79,201.3 | 17.14,201.3 D31.A | 23.5,201.3 17.14,201.3 | 23.5,201.3 D43.A | 29.84,201.3 23.5,201.3 | 29.84,201.3 D55.A | 36.2,201.3 29.84,201.3 | 36.2,201.3 D67.A | 42.55,201.3 36.2,201.3 | 42.55,201.3 D79.A | 48.9,201.3 42.55,201.3 | D91.A 48.9,201.3 | 48.9,201.3 55.24,201.3 | 55.24,201.3 D103.A | 55.24,201.3 61.59,201.3 | 61.59,201.3 D115.A | 61.59,201.3 67.94,201.3 | 67.94,201.3 D127.A | 67.94,201.3 74.3,201.3 | 74.3,201.3 D139.A | 74.3,201.3 80.64,201.3 | 80.64,201.3 D151.A | 80.64,201.3 87,201.3 | 87,201.3 D163.A | 87,201.3 93.34,201.3 | 93.34,201.3 D175.A | 93.34,201.3 99.69,201.3 | 99.69,201.3 D187.A | v98.42,39.37 115.57,39.37 116.2,40.01 122.56,40.01 123.19,39.37 137.16,39.37 138.43,38.1 E17.11
N$39
  Top 0.254: E35.5 6.99,36.2 6.99,37.47 E35.4 4.45,41.28 4.45,169.55 6.35,171.45 D9.A
  Bottom 0.254: 167,170.82 164.47,170.82 D201.A 162.56,173.99 149.22,173.99 147.96,172.72 R48.2 146.69,172.72 144.78,170.82 99.69,170.82 | 167,170.82 D213.A | 167,170.82 173.35,170.82 | 173.35,170.82 D225.A | 173.35,170.82 179.71,170.82 | 179.71,170.82 D237.A | 179.71,170.82 186.06,170.82 | 186.06,170.82 D249.A | 186.06,170.82 192.41,170.82 | 192.41,170.82 D261.A | 192.41,170.82 198.75,170.82 | 198.75,170.82 D273.A | 198.75,170.82 205.1,170.82 | 205.1,170.82 D285.A | 205.1,170.82 211.46,170.82 | 211.46,170.82 D297.A | 211.46,170.82 217.81,170.82 | 217.81,170.82 D309.A | 217.81,170.82 224.16,170.82 | 224.16,170.82 D321.A | 224.16,170.82 230.5,170.82 | 230.5,170.82 D333.A | 230.5,170.82 236.85,170.82 | 236.85,170.82 D345.A | 236.85,170.82 243.21,170.82 | 243.21,170.82 D357.A | 243.21,170.82 249.56,170.82 | 249.56,170.82 D369.A | 249.56,170.82 255.91,170.82 D381.A | 10.79,170.82 8.26,170.82 D9.A | 10.79,170.82 D21.A | 17.14,170.82 10.79,170.82 | 17.14,170.82 D33.A | 23.5,170.82 17.14,170.82 | 23.5,170.82 D45.A | 29.84,170.82 23.5,170.82 | 29.84,170.82 D57.A | 36.2,170.82 29.84,170.82 | 36.2,170.82 D69.A | 42.55,170.82 36.2,170.82 | 42.55,170.82 D81.A | 48.9,170.82 42.55,170.82 | 48.9,170.82 D93.A | 55.24,170.82 48.9,170.82 | 55.24,170.82 D105.A | 61.59,170.82 55.24,170.82 | 61.59,170.82 D117.A | 67.94,170.82 61.59,170.82 | 67.94,170.82 D129.A | 74.3,170.82 67.94,170.82 | 74.3,170.82 D141.A | 80.64,170.82 74.3,170.82 | D153.A 80.64,170.82 | 80.64,170.82 87,170.82 | 87,170.82 D165.A | 87,170.82 93.34,170.82 | 93.34,170.82 D177.A | 93.34,170.82 99.69,170.82 | 99.69,170.82 D189.A
N$40
  Top 0.254: E17.6 131.44,32.39 131.44,31.12 E17.7 130.18,28.58 130.18,18.42 128.91,17.15 125.09,17.15 125.09,32.39 117.47,40.01 117.47,74.3 114.3,77.47 114.3,100.97 112.39,102.87 112.39,106.05 110.49,107.95 107.31,107.95 107.31,111.13 102.87,115.57 102.87,124.46 104.14,125.73 D186.A
  Bottom 0.254: 167,128.91 169.54,128.91 | 167,128.91 D198.A | 169.54,128.91 D210.A | 169.54,128.91 175.9,128.91 | 175.9,128.91 D222.A | 175.9,128.91 182.25,128.91 | 182.25,128.91 D234.A | 182.25,128.91 188.59,128.91 | 188.59,128.91 D246.A | 188.59,128.91 194.94,128.91 | 194.94,128.91 D258.A | 194.94,128.91 201.29,128.91 | 201.29,128.91 D270.A | 201.29,128.91 207.65,128.91 | 207.65,128.91 D282.A | 207.65,128.91 214,128.91 | 214,128.91 D294.A | 214,128.91 220.34,128.91 | 220.34,128.91 D306.A | 220.34,128.91 226.69,128.91 | 226.69,128.91 D318.A | 226.69,128.91 233.04,128.91 | 233.04,128.91 D330.A | 233.04,128.91 239.4,128.91 | 239.4,128.91 D342.A | 239.4,128.91 245.75,128.91 | 245.75,128.91 D354.A | 245.75,128.91 252.09,128.91 | 252.09,128.91 D366.A | 252.09,128.91 258.44,128.91 D378.A | 167,128.91 158.75,128.91 155.57,132.08 R45.2 154.31,132.08 150.5,128.27 104.14,128.27 D186.A 102.23,128.91 95.89,128.91 | 13.34,128.91 10.79,128.91 D6.A | 13.34,128.91 D18.A | 19.68,128.91 13.34,128.91 | 19.68,128.91 D30.A | 26.04,128.91 19.68,128.91 | 26.04,128.91 D42.A | 32.38,128.91 26.04,128.91 | 32.38,128.91 D54.A | 38.73,128.91 32.38,128.91 | 38.73,128.91 D66.A | 45.09,128.91 38.73,128.91 | 45.09,128.91 D78.A | 51.44,128.91 45.09,128.91 | 51.44,128.91 D90.A | 57.78,128.91 51.44,128.91 | 57.78,128.91 D102.A | 64.14,128.91 57.78,128.91 | 64.14,128.91 D114.A | 70.48,128.91 64.14,128.91 | 70.48,128.91 D126.A | 76.83,128.91 70.48,128.91 | 76.83,128.91 D138.A | 83.19,128.91 76.83,128.91 | 83.19,128.91 D150.A | 89.53,128.91 83.19,128.91 | 89.53,128.91 D162.A | 95.89,128.91 89.53,128.91 | 95.89,128.91 D174.A
N$41  (via drill 0.61)
  Top 0.254: E17.5 131.44,36.2 131.44,37.47 E17.4 135.89,41.91 135.89,54.61 144.15,62.87 144.15,71.76 146.69,74.3 146.69,103.51 147.32,104.14 147.32,122.56 148.59,123.83 148.59,140.34 149.86,141.61 R44.2 | v162.56,139.7 D197.A
  Bottom 0.254: 13.34,144.15 10.79,144.15 D5.A | 13.34,144.15 D17.A | 19.68,144.15 13.34,144.15 | 19.68,144.15 D29.A | 26.04,144.15 19.68,144.15 | 26.04,144.15 D41.A | 32.38,144.15 26.04,144.15 | 32.38,144.15 D53.A | 38.73,144.15 32.38,144.15 | 38.73,144.15 D65.A | 45.09,144.15 38.73,144.15 | 45.09,144.15 D77.A | 51.44,144.15 45.09,144.15 | 51.44,144.15 D89.A | 57.78,144.15 51.44,144.15 | 57.78,144.15 D101.A | 64.14,144.15 57.78,144.15 | 64.14,144.15 D113.A | 70.48,144.15 64.14,144.15 | 70.48,144.15 D125.A | 76.83,144.15 70.48,144.15 | 76.83,144.15 D137.A | 83.19,144.15 76.83,144.15 | 83.19,144.15 D149.A | 89.53,144.15 83.19,144.15 | 89.53,144.15 D161.A | 95.89,144.15 89.53,144.15 | 95.89,144.15 D173.A | 95.89,144.15 102.23,144.15 D185.A 106.05,144.15 167,144.15 | v162.56,139.7 153.03,139.7 150.5,142.24 R44.2 | 167,144.15 169.54,144.15 | 169.54,144.15 D209.A | D197.A 167,144.15 | 169.54,144.15 175.9,144.15 | 175.9,144.15 D221.A | 175.9,144.15 182.25,144.15 | 182.25,144.15 D233.A | 182.25,144.15 188.59,144.15 | 188.59,144.15 D245.A | 188.59,144.15 194.94,144.15 | 194.94,144.15 D257.A | 194.94,144.15 201.29,144.15 | 201.29,144.15 D269.A | 201.29,144.15 207.65,144.15 | 207.65,144.15 D281.A | 207.65,144.15 214,144.15 | 214,144.15 D293.A | 214,144.15 220.34,144.15 | 220.34,144.15 D305.A | 220.34,144.15 226.69,144.15 | 226.69,144.15 D317.A | 226.69,144.15 233.04,144.15 | 233.04,144.15 D329.A | 233.04,144.15 239.4,144.15 | 239.4,144.15 D341.A | 239.4,144.15 245.75,144.15 | 245.75,144.15 D353.A | 245.75,144.15 252.09,144.15 | 252.09,144.15 D365.A | 252.09,144.15 258.44,144.15 D377.A
N$42  (via drill 0.61)
  Top 0.254: E1.7 243.21,31.12 243.21,32.39 E1.6 240.03,36.83 240.03,112.4 236.22,116.21 236.22,154.94 234.95,156.21 D328.A | D196.A v165.1,154.31
  Bottom 0.254: 13.34,159.39 10.79,159.39 D4.A | 13.34,159.39 D16.A | 19.68,159.39 13.34,159.39 | 19.68,159.39 D28.A | 26.04,159.39 19.68,159.39 | 26.04,159.39 D40.A | 32.38,159.39 26.04,159.39 | 32.38,159.39 D52.A | 38.73,159.39 32.38,159.39 | 38.73,159.39 D64.A | 45.09,159.39 38.73,159.39 | 45.09,159.39 D76.A | 51.44,159.39 45.09,159.39 | 51.44,159.39 D88.A | 57.78,159.39 51.44,159.39 | 57.78,159.39 D100.A | 64.14,159.39 57.78,159.39 | 64.14,159.39 D112.A | 70.48,159.39 64.14,159.39 | 70.48,159.39 D124.A | 76.83,159.39 70.48,159.39 | 76.83,159.39 D136.A | 83.19,159.39 76.83,159.39 | 83.19,159.39 D148.A | 89.53,159.39 83.19,159.39 | 89.53,159.39 D160.A | 95.89,159.39 89.53,159.39 | D172.A 95.89,159.39 | 95.89,159.39 102.23,159.39 D184.A 106.05,159.39 167,159.39 | v165.1,154.31 153.67,154.31 150.5,157.48 R43.2 | 167,159.39 169.54,159.39 | 169.54,159.39 D208.A | 167,159.39 D196.A | 169.54,159.39 175.9,159.39 | 175.9,159.39 D220.A | 175.9,159.39 182.25,159.39 | 182.25,159.39 D232.A | 182.25,159.39 188.59,159.39 | 188.59,159.39 D244.A | 188.59,159.39 194.94,159.39 | 194.94,159.39 D256.A | 194.94,159.39 201.29,159.39 | 201.29,159.39 D268.A | 201.29,159.39 207.65,159.39 | 207.65,159.39 D280.A | 207.65,159.39 214,159.39 | 214,159.39 D292.A | 214,159.39 220.34,159.39 | 220.34,159.39 D304.A | 220.34,159.39 226.69,159.39 | 226.69,159.39 D316.A | 226.69,159.39 233.04,159.39 | 233.04,159.39 D328.A | 233.04,159.39 239.4,159.39 | 239.4,159.39 D340.A | 239.4,159.39 245.75,159.39 | 245.75,159.39 D352.A | 245.75,159.39 252.09,159.39 | 252.09,159.39 D364.A | 252.09,159.39 258.44,159.39 D376.A
N$43  (via drill 0.61)
  Top 0.254: E1.5 243.21,36.2 243.21,37.47 E1.4 247.01,41.28 247.01,112.4 242.57,116.84 242.57,170.18 241.3,171.45 D339.A | D195.A v162.56,170.18
  Bottom 0.254: 13.34,174.63 10.79,174.63 D3.A | 13.34,174.63 D15.A | 19.68,174.63 13.34,174.63 | 19.68,174.63 D27.A | 26.04,174.63 19.68,174.63 | 26.04,174.63 D39.A | 32.38,174.63 26.04,174.63 | 32.38,174.63 D51.A | 38.73,174.63 32.38,174.63 | 38.73,174.63 D63.A | 45.09,174.63 38.73,174.63 | 45.09,174.63 D75.A | 51.44,174.63 45.09,174.63 | 51.44,174.63 D87.A | 57.78,174.63 51.44,174.63 | 57.78,174.63 D99.A | 64.14,174.63 57.78,174.63 | 64.14,174.63 D111.A | 70.48,174.63 64.14,174.63 | 70.48,174.63 D123.A | 76.83,174.63 70.48,174.63 | 76.83,174.63 D135.A | 83.19,174.63 76.83,174.63 | 83.19,174.63 D147.A | 83.19,174.63 89.53,174.63 | 89.53,174.63 D159.A | 89.53,174.63 95.89,174.63 | 95.89,174.63 D171.A | 95.89,174.63 102.23,174.63 D183.A 106.05,174.63 167,174.63 | v162.56,170.18 153.03,170.18 150.5,172.72 R42.2 | 167,174.63 169.54,174.63 | 169.54,174.63 D207.A | 167,174.63 D195.A | 169.54,174.63 175.9,174.63 | 175.9,174.63 D219.A | 175.9,174.63 182.25,174.63 | 182.25,174.63 D231.A | 182.25,174.63 188.59,174.63 | 188.59,174.63 D243.A | 188.59,174.63 194.94,174.63 | 194.94,174.63 D255.A | 194.94,174.63 201.29,174.63 | 201.29,174.63 D267.A | 201.29,174.63 207.65,174.63 | 207.65,174.63 D279.A | 207.65,174.63 214,174.63 | 214,174.63 D291.A | 214,174.63 220.34,174.63 | 220.34,174.63 D303.A | 220.34,174.63 226.69,174.63 | 226.69,174.63 D315.A | 226.69,174.63 233.04,174.63 | 233.04,174.63 D327.A | 233.04,174.63 239.4,174.63 | 239.4,174.63 D339.A | 239.4,174.63 245.75,174.63 | 245.75,174.63 D351.A | 245.75,174.63 252.09,174.63 | 252.09,174.63 D363.A | 252.09,174.63 258.44,174.63 D375.A
N$44
  Top 0.254: E1.9 250.82,33.66 250.82,34.93 E1.10 255.91,40.01 255.91,184.79 254,186.69 D362.A | 166.37,193.04 166.37,190.5 165.1,189.23 D194.A | 166.37,193.04 166.37,198.76 161.29,198.76 150.5,187.96 R41.2 | 166.37,193.04 D206.A
  Bottom 0.254: 13.34,189.87 10.79,189.87 D2.A | 13.34,189.87 D14.A | 19.68,189.87 13.34,189.87 | 19.68,189.87 D26.A | 26.04,189.87 19.68,189.87 | 26.04,189.87 D38.A | 32.38,189.87 26.04,189.87 | 32.38,189.87 D50.A | 38.73,189.87 32.38,189.87 | 38.73,189.87 D62.A | 45.09,189.87 38.73,189.87 | 45.09,189.87 D74.A | 51.44,189.87 45.09,189.87 | 51.44,189.87 D86.A | 57.78,189.87 51.44,189.87 | 57.78,189.87 D98.A | 64.14,189.87 57.78,189.87 | D110.A 64.14,189.87 | 64.14,189.87 70.48,189.87 | 70.48,189.87 D122.A | 70.48,189.87 76.83,189.87 | 76.83,189.87 D134.A | 76.83,189.87 83.19,189.87 | 83.19,189.87 D146.A | 83.19,189.87 89.53,189.87 | 89.53,189.87 D158.A | 89.53,189.87 95.89,189.87 | 95.89,189.87 D170.A | 95.89,189.87 102.23,189.87 D182.A 106.05,189.87 163.19,189.87 D194.A | 175.9,189.87 173.35,189.87 D206.A | 175.9,189.87 D218.A | 175.9,189.87 182.25,189.87 | 182.25,189.87 D230.A | 182.25,189.87 188.59,189.87 | 188.59,189.87 D242.A | 188.59,189.87 194.94,189.87 | 194.94,189.87 D254.A | 194.94,189.87 201.29,189.87 | 201.29,189.87 D266.A | 201.29,189.87 207.65,189.87 | 207.65,189.87 D278.A | 207.65,189.87 214,189.87 | 214,189.87 D290.A | 214,189.87 220.34,189.87 | 220.34,189.87 D302.A | 220.34,189.87 226.69,189.87 | 226.69,189.87 D314.A | 226.69,189.87 233.04,189.87 | 233.04,189.87 D326.A | 233.04,189.87 239.4,189.87 | 239.4,189.87 D338.A | 239.4,189.87 245.75,189.87 | 245.75,189.87 D350.A | 245.75,189.87 252.09,189.87 | 252.09,189.87 D362.A | 252.09,189.87 258.44,189.87 D374.A
N$45  (via drill 0.61)
  Top 0.254: v144.15,35.56 144.15,38.74 E17.13
  Bottom 0.254: v144.15,35.56 E14.5
N$46
  Bottom 0.254: E17.2 133.35,43.18 134.62,41.91 143.51,41.91 146.05,39.37 152.4,39.37 153.67,38.1 E14.11
N$47  (via drill 0.61)
  Top 0.254: v130.18,34.29 130.18,38.74 E17.3
  Bottom 0.254: v130.18,34.29 156.21,34.29 156.84,33.66 156.84,31.12 155.57,31.12 E14.8
N$48
  Bottom 0.254: E4.2 233.68,43.18 234.95,44.45 241.3,44.45 242.57,43.18 E1.2
N$49
  Bottom 0.254: E4.5 229.87,35.56 233.68,39.37 241.3,39.37 242.57,40.64 E1.3
N$50
  Bottom 0.254: E4.11 237.49,38.1 238.12,38.74 241.94,38.74 242.57,39.37 245.11,39.37 E1.14
N$51
  Bottom 0.254: E4.8 242.57,36.83 245.11,36.83 E1.13
N$52
  Bottom 0.254: E35.14 16.51,45.72 19.05,43.18 E32.2
N$53  (via drill 0.61)
  Top 0.254: v20.32,41.91 20.32,38.1 E32.5
  Bottom 0.254: v20.32,41.91 19.68,42.55 15.88,42.55 E35.13
N$54
  Bottom 0.254: E35.2 8.89,43.18 10.16,41.91 19.05,41.91 21.59,39.37 27.94,39.37 29.21,38.1 E32.11
N$55
  Bottom 0.254: E35.3 5.71,38.74 5.71,29.21 27.94,29.21 29.21,30.48 E32.8
N$56
  Bottom 0.254: E17.14 140.97,45.72 143.51,43.18 E14.2
N$57
  Top 0.254: R29.2 109.22,188.6 110.49,189.87 T1.2
N$58
  Bottom 0.254: E36.11 16.51,71.12 17.78,72.39 42.55,72.39 43.81,71.12 E30.11
N$59
  Bottom 0.254: E36.3 8.89,73.66 10.16,74.93 35.56,74.93 36.83,73.66 E30.3
N$60  (via drill 0.61)
  Top 0.254: v95.89,75.57 100.97,80.65 100.97,106.05 v106.05,111.13
  Bottom 0.254: v95.89,75.57 70.48,75.57 69.85,76.2 E27.13 | v106.05,111.13 107.95,113.03 127,113.03 128.27,111.76 E19.2
N$61  (via drill 0.61)
  Top 0.254: v125.09,72.39 124.46,73.03 124.46,80.65 130.18,86.36 v130.18,87.63 | v177.8,88.9 E10.6
  Bottom 0.254: v125.09,72.39 128.27,72.39 128.91,73.03 132.72,73.03 133.35,73.66 E18.3 | v130.18,87.63 131.44,88.9 v177.8,88.9
N$62  (via drill 0.61)
  Top 0.254: v48.26,64.77 46.99,63.5 E30.8
  Bottom 0.254: E36.4 5.71,69.22 5.71,60.96 41.91,60.96 44.45,63.5 E30.8 | v48.26,64.77 69.85,64.77 70.48,64.14 100.97,64.14 102.87,66.04 E22.6
N$63  (via drill 0.61)
  Top 0.254: E21.6 103.5,36.2 v103.5,60.33 103.5,61.6 102.23,62.87 102.23,66.68 E22.5 | v154.94,66.04 154.94,73.66 E15.13
  Bottom 0.254: E36.5 8.89,68.58 10.16,69.85 101.6,69.85 102.87,68.58 E22.5 | v154.94,66.04 149.22,60.33 v103.5,60.33
N$64
  Bottom 0.254: E22.9 113.03,66.04 114.3,64.77 147.32,64.77 148.59,66.04 E15.6 151.13,66.04 152.4,67.31 162.56,67.31 163.83,66.04 E12.6
N$65
  Top 0.254: C1.1 142.24,102.24 139.06,105.41 139.06,107.32 E19.14
N$66
  pour Top: 130.81,187.96 129.54,185.42 128.27,187.96
  pour Top: 130.81,184.79 130.81,185.42 128.27,185.42 128.27,184.79
N$67
  pour Top: 134.62,187.96 133.35,185.42 132.08,187.96
  pour Top: 134.62,184.79 134.62,185.42 132.08,185.42 132.08,184.79
N$68
  pour Top: 130.81,180.34 129.54,177.8 128.27,180.34
  pour Top: 130.81,177.17 130.81,177.8 128.27,177.8 128.27,177.17
N$69
  Top 0.254: E31.6 36.83,90.17 33.66,90.17 33.66,94.62 34.29,95.25 37.47,95.25 37.47,102.24 E34.13
N$70
  Bottom 0.254: E10.11 191.77,99.06 194.31,96.52 E9.5
N$71
  Top 0.254: E10.9 E9.6
N$72  (via drill 0.61)
  Top 0.254: v226.69,102.87 226.69,95.89 E6.6
  Bottom 0.254: v226.69,102.87 241.3,102.87 242.57,101.6 E3.3
N$73
  Bottom 0.254: E34.3 29.21,101.6 30.48,100.33 38.1,100.33 39.37,99.06 E31.4
N$74
  Bottom 0.254: E34.1 26.04,104.78 26.04,97.79 36.83,97.79 38.1,96.52 E31.5
N$75
  Bottom 0.254: E34.11 36.83,99.06 38.1,97.79 45.72,97.79 46.99,96.52 E31.10
N$76
  Bottom 0.254: E34.9 36.83,93.98 38.1,95.25 49.53,95.25 50.16,95.89 50.16,98.43 48.9,98.43 E31.11
N$77
  Bottom 0.254: E31.12 49.53,101.6 54.61,96.52 E28.5
N$78
  Bottom 0.254: E28.1 57.15,106.68 58.42,107.95 67.31,107.95 69.85,105.41 72.39,105.41 73.03,104.78 73.03,102.24 71.75,102.24 E25.3
N$79
  Bottom 0.254: E28.13 64.77,104.14 69.85,99.06 E25.4
N$80
  Bottom 0.254: E28.11 64.77,99.06 66.04,97.79 68.58,97.79 69.85,96.52 E25.5
N$81
  Bottom 0.254: E28.9 E25.6
N$82
  Bottom 0.254: E25.10 76.2,99.06 76.2,105.41 81.92,105.41 83.19,106.68 E24.1
N$83
  Bottom 0.254: E10.1 184.15,106.68 185.42,107.95 194.31,107.95 196.85,105.41 199.39,105.41 200.03,104.78 200.03,102.24 198.75,102.24 E9.3
N$84
  Bottom 0.254: E8.11 222.25,99.06 224.79,101.6 E6.3
N$85
  Bottom 0.254: E6.12 237.49,101.6 238.76,100.33 248.92,100.33 250.19,99.06 E3.11
N$86
  Bottom 0.254: E6.11 237.49,99.06 238.12,98.43 241.94,98.43 242.57,97.79 252.73,97.79 253.37,98.43 253.37,103.51 252.09,103.51 E3.13
N$87  (via drill 0.61)
  Top 0.254: v238.76,106.68 238.76,99.06 E6.10
  Bottom 0.254: v238.76,106.68 E3.1
N$88
  Bottom 0.254: E25.11 76.83,100.97 76.83,102.87 88.9,102.87 90.17,104.14 E24.13
N$89
  Bottom 0.254: E25.12 80.01,101.6 81.28,100.33 91.44,100.33 92.71,99.06 E24.11
N$90
  Top 0.254: E10.13 191.77,104.14 196.85,99.06 E9.4
N$91
  Bottom 0.254: E9.10 E8.5
N$92
  Bottom 0.254: E9.11 207.01,99.06 209.55,101.6 E8.3
N$93
  Bottom 0.254: E9.12 203.84,103.51 203.84,105.41 210.82,105.41 212.09,106.68 E8.1
N$94
  Top 0.254: E8.9 219.07,92.08 219.07,90.17 226.69,82.55 230.5,82.55 230.5,97.16 E6.4
N$95
  Bottom 0.254: E6.5 229.87,96.52 231.14,97.79 241.3,97.79 242.57,96.52 E3.5
N$96
  Top 0.254: E6.2 227.97,104.78 227.97,106.05 E6.1
  Bottom 0.254: E9.13 207.01,104.14 207.65,104.78 211.46,104.78 212.09,105.41 218.44,105.41 219.71,104.14 E8.13 E6.2
N$97  (via drill 0.61)
  Top 0.254: E9.2 197.49,104.78 197.49,106.05 E9.1 | v92.08,105.41 92.08,95.89 E24.9
  Bottom 0.254: E25.13 81.92,104.14 83.19,105.41 v92.08,105.41 195.58,105.41 196.85,104.14 E9.2
N$98
  Top 0.254: E25.2 70.48,104.78 70.48,106.05 E25.1
  Bottom 0.254: E31.13 52.07,104.14 54.61,101.6 E28.3 58.42,101.6 62.23,105.41 68.58,105.41 69.85,104.14 E25.2
N$99
  pour Top: 134.62,180.34 133.35,177.8 132.08,180.34
  pour Top: 134.62,177.17 134.62,177.8 132.08,177.8 132.08,177.17
N$100
  pour Top: 130.81,172.72 129.54,170.18 128.27,172.72
  pour Top: 130.81,169.55 130.81,170.18 128.27,170.18 128.27,169.55
N$101
  pour Top: 134.62,172.72 133.35,170.18 132.08,172.72
  pour Top: 134.62,169.55 134.62,170.18 132.08,170.18 132.08,169.55
N$102
  pour Top: 130.81,165.1 129.54,162.56 128.27,165.1
  pour Top: 130.81,161.93 130.81,162.56 128.27,162.56 128.27,161.93
N$103
  pour Top: 134.62,165.1 133.35,162.56 132.08,165.1
  pour Top: 134.62,161.93 134.62,162.56 132.08,162.56 132.08,161.93
N$104
  pour Top: 130.81,157.48 129.54,154.94 128.27,157.48
  pour Top: 130.81,154.31 130.81,154.94 128.27,154.94 128.27,154.31
N$105
  pour Top: 134.62,157.48 133.35,154.94 132.08,157.48
  pour Top: 134.62,154.31 134.62,154.94 132.08,154.94 132.08,154.31
N$106
  Top 0.254: 106.68,207.01 127,207.01 | 106.68,207.01 107.95,205.74 107.95,208.28 106.68,207.01
N$107
  Top 0.254: 135.89,207.01 160.02,207.01 | 160.02,207.01 158.75,208.28 158.75,205.74 160.02,207.01
N$108
  pour Top: 130.81,195.58 129.54,193.04 128.27,195.58
  pour Top: 130.81,192.41 130.81,193.04 128.27,193.04 128.27,192.41
N$109
  pour Top: 134.62,195.58 133.35,193.04 132.08,195.58
  pour Top: 134.62,192.41 134.62,193.04 132.08,193.04 132.08,192.41
N$110
  Top 0.254: 125.73,196.85 124.46,198.12 127,198.12 125.73,196.85 | 125.73,196.85 125.73,200.66 127,200.66
N$111
  Top 0.254: 137.16,196.85 135.89,198.12 138.43,198.12 137.16,196.85 | 137.16,196.85 137.16,200.66 135.89,200.66
N$112
  Top 0.254: R31.2 C1.2
  Bottom 0.254: E19.15 138.43,111.76 140.97,109.22 R31.2
N$113
  Bottom 0.254: C3.1 E19.6
N$114
  Top 0.254: R32.1 50.8,74.3 50.16,74.93 50.16,89.54 C2.-
  Bottom 0.254: R32.1 R33.2
N$115
  Top 0.254: R33.1 R35.1 E27.7 60.33,64.14 60.33,65.41 E27.6
N$116
  Top 0.254: E33.3 20.95,71.76 20.95,70.49 E33.5
  Bottom 0.254: E36.6 8.89,66.04 10.16,67.31 20.32,67.31 21.59,68.58 E33.5
N$117  (via drill 0.61)
  Top 0.254: v60.33,98.43 60.33,90.81 63.5,87.63 63.5,78.74 E27.2
  Bottom 0.254: v60.33,98.43 62.23,100.33 67.31,100.33 69.85,97.79 74.93,97.79 77.47,95.25 81.92,95.25 83.19,96.52 E24.5
N$118  (via drill 0.61)
  Top 0.254: v83.82,77.47 83.82,79.38 85.09,80.65 85.09,87.63 | 85.09,87.63 85.09,90.17 84.45,90.81 84.45,92.08 E24.6 | v90.17,97.79 89.53,97.16 89.53,92.08 85.09,87.63
  Bottom 0.254: v83.82,77.47 59.05,77.47 55.88,74.3 R35.2 | v90.17,97.79 134.62,97.79 135.89,99.06 E19.10
N$119
  Top 0.254: R34.2 C3.2 124.46,104.14 E19.7
N$120
  Top 0.254: E18.8 139.7,66.04 139.7,91.44 133.99,97.16 133.99,109.86 E19.1
N$121
  Top 0.254: R36.2 C4.2
  Bottom 0.254: E37.7 8.89,91.44 12.7,95.25 20.95,95.25 22.23,96.52 R36.2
